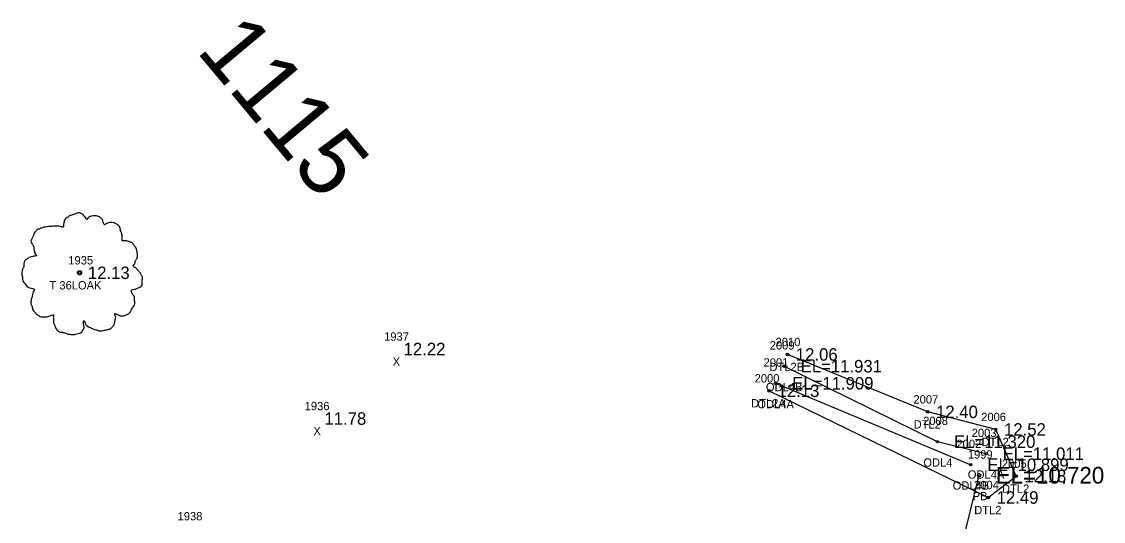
# Model space of a CAD drawing. Extents: x 2042117 to 2045853, y 303080 to 309569.
# Drawn here: x 2044100.5 to 2044230.3, y 305233.1 to 305293.1 of the extents above; entities that cross this region are included whole.
import ezdxf

# ---------------------------------------------------------------- set-up
doc = ezdxf.new("R2010")
doc.units = 0
for name, color, linetype in [('RD_EX_DR_Pipe', 7, 'Continuous'), ('RD_EX_DR_Pipe_txCode', 7, 'Continuous'), ('RD_EX_H2O', 7, 'Continuous'), ('RD_EX_H2O_txCode', 7, 'Continuous'), ('RD_EX_Misc_txCode', 7, 'Continuous'), ('RD_EX_TX_H2O_ELEV', 7, 'Continuous'), ('RD_EX_TX_Misc_ELEV', 7, 'Continuous'), ('RD_EX_TX_VEG_ELEV', 7, 'Continuous'), ('RD_EX_VEG', 7, 'Continuous'), ('RD_EX_VEG_txCode', 7, 'Continuous'), ('RD_HC_TX_Sta50', 7, 'Continuous'), ('RD_SMD_Locator', 7, 'Continuous'), ('RD_TX_Pipe_ElevEX', 7, 'Continuous')]:
    doc.layers.add(name, color=color, linetype=linetype)

msp = doc.modelspace()

# ---------------------------------------------------------------- linework, layer by layer
at = {"layer": 'RD_EX_DR_Pipe'}
msp.add_line((2044209.68, 305215.41), (2044215.36, 305238.61), dxfattribs=at)
at = {"layer": 'RD_EX_H2O'}
msp.add_line((2044190.92, 305249.65), (2044214.35, 305239.88), dxfattribs=at)
for points in [[(2044190.17, 305248.75), (2044216.46, 305235.94), (2044219.8, 305238.51), (2044217.35, 305244.11), (2044209.19, 305246.22), (2044192.36, 305253.11)], [(2044216.18, 305241.2), (2044210.35, 305242.64), (2044191.94, 305251.7)]]:
    msp.add_lwpolyline(points, dxfattribs=at)
at = {"layer": 'RD_EX_VEG'}
for centre, radius in [((2044107.4, 305262.91), 0.25), ((2044107.39, 305262.89), 0.0001)]:
    msp.add_circle(centre, radius, dxfattribs=at)
for points in [[(2044107.53, 305270.08), (2044107.23, 305270.1), (2044106.91, 305270), (2044106.66, 305269.9), (2044106.43, 305269.83), (2044106.21, 305269.73), (2044105.91, 305269.55), (2044105.68, 305269.35), (2044105.56, 305269.1), (2044105.51, 305268.88), (2044105.46, 305268.6), (2044105.46, 305268.43), (2044105.33, 305268.4), (2044105.18, 305268.43), (2044104.93, 305268.5), (2044104.68, 305268.5), (2044104.43, 305268.5), (2044104.08, 305268.48), (2044103.73, 305268.48), (2044103.46, 305268.43), (2044103.13, 305268.38), (2044102.76, 305268.25), (2044102.41, 305268.13), (2044102.11, 305267.88), (2044101.86, 305267.4), (2044101.73, 305267.05), (2044101.58, 305266.8), (2044101.73, 305266.35), (2044101.91, 305266), (2044101.93, 305265.8), (2044102.01, 305265.38), (2044102.11, 305265.16), (2044102.23, 305264.96), (2044102.16, 305264.93), (2044101.78, 305264.88), (2044101.48, 305264.78), (2044101.06, 305264.56), (2044100.83, 305264.33), (2044100.73, 305264.01), (2044100.71, 305263.66), (2044100.61, 305263.46), (2044100.53, 305263.18), (2044100.51, 305263.11), (2044100.46, 305262.78), (2044100.56, 305262.33), (2044100.58, 305261.98), (2044100.71, 305261.76), (2044100.86, 305261.58), (2044101.03, 305261.33), (2044101.43, 305261.11), (2044101.76, 305261.01), (2044101.96, 305260.98), (2044101.78, 305260.48), (2044101.73, 305260.13), (2044101.61, 305259.73), (2044101.61, 305259.66), (2044101.56, 305259.18), (2044101.71, 305258.86), (2044101.78, 305258.48), (2044101.96, 305258.26), (2044102.23, 305257.96), (2044102.56, 305257.73), (2044103.06, 305257.61), (2044103.46, 305257.63), (2044104.03, 305257.81), (2044104.28, 305257.88), (2044104.26, 305257.71), (2044104.28, 305257.33), (2044104.28, 305256.91), (2044104.43, 305256.58), (2044104.53, 305256.31), (2044104.68, 305256.06), (2044105.01, 305255.83), (2044105.41, 305255.76), (2044105.83, 305255.61), (2044106.28, 305255.53), (2044106.78, 305255.51), (2044107.38, 305255.66), (2044107.65, 305255.78), (2044107.75, 305255.96), (2044107.95, 305256.33), (2044107.9, 305256.56), (2044107.93, 305257.16), (2044108.03, 305256.98), (2044108.2, 305256.63), (2044108.7, 305256.33), (2044109.1, 305256.16), (2044109.58, 305256.01), (2044109.88, 305255.93), (2044110.35, 305256.01), (2044110.73, 305256.08), (2044111.1, 305256.21), (2044111.4, 305256.48), (2044111.58, 305256.76), (2044111.63, 305257.03), (2044111.7, 305257.41), (2044111.75, 305257.58)], [(2044111.75, 305257.58), (2044111.68, 305257.76), (2044111.63, 305258.01), (2044111.7, 305257.98), (2044111.88, 305257.93), (2044112.15, 305257.81), (2044112.38, 305257.73), (2044112.7, 305257.76), (2044112.98, 305257.86), (2044113.43, 305258.13), (2044113.7, 305258.61), (2044113.98, 305259.01), (2044114.05, 305259.33), (2044114, 305259.56), (2044113.98, 305260.06), (2044113.78, 305260.31), (2044113.73, 305260.43), (2044113.63, 305260.83), (2044113.7, 305260.88), (2044113.98, 305260.93), (2044114.35, 305261.06), (2044114.63, 305261.18), (2044114.85, 305261.36), (2044114.93, 305261.58), (2044114.9, 305261.98), (2044114.95, 305262.38), (2044114.88, 305262.53), (2044114.78, 305262.68), (2044114.7, 305262.88), (2044114.55, 305263.03), (2044114.45, 305263.18), (2044114.35, 305263.28), (2044114.23, 305263.43), (2044114.05, 305263.56), (2044113.9, 305263.61), (2044113.85, 305263.76), (2044114, 305263.96), (2044114.05, 305264.06), (2044114.08, 305264.28), (2044114.3, 305264.63), (2044114.35, 305265.03), (2044114.3, 305265.46), (2044114.25, 305265.73), (2044114.1, 305266), (2044113.9, 305266.25), (2044113.78, 305266.43), (2044113.6, 305266.55), (2044113.28, 305266.68), (2044113.03, 305266.73), (2044112.68, 305266.73), (2044112.48, 305266.78), (2044112.5, 305266.83), (2044112.5, 305266.98), (2044112.5, 305267.25), (2044112.43, 305267.7), (2044112.28, 305268.2), (2044112.28, 305268.23), (2044112.18, 305268.48), (2044111.95, 305268.68), (2044111.78, 305268.78), (2044111.58, 305268.9), (2044111.33, 305268.93), (2044111.03, 305268.93), (2044110.75, 305268.88), (2044110.55, 305268.78), (2044110.38, 305268.65), (2044110.3, 305268.8), (2044110.2, 305269.1), (2044110.15, 305269.25), (2044110, 305269.43), (2044109.78, 305269.63), (2044109.33, 305269.75), (2044108.7, 305269.68), (2044108.4, 305269.48), (2044108.25, 305269.3), (2044108.2, 305269.43), (2044108, 305269.63), (2044107.9, 305269.8), (2044107.73, 305269.93), (2044107.58, 305270.03), (2044107.48, 305270.08)]]:
    msp.add_spline(points, degree=3, dxfattribs=at)
at = {"layer": 'RD_SMD_Locator'}
for centre, radius in [((2044107.4, 305262.91), 0.15), ((2044192.36, 305253.11), 0.15), ((2044191.94, 305251.7), 0.15), ((2044190.92, 305249.65), 0.15), ((2044190.17, 305248.75), 0.15), ((2044209.19, 305246.22), 0.15), ((2044217.35, 305244.11), 0.15), ((2044210.35, 305242.64), 0.15), ((2044216.18, 305241.2), 0.15), ((2044214.35, 305239.88), 0.15), ((2044215.36, 305238.61), 0.2), ((2044219.8, 305238.51), 0.15), ((2044216.46, 305235.94), 0.15)]:
    msp.add_circle(centre, radius, dxfattribs=at)

# ---------------------------------------------------------------- texts
at = {"layer": 'RD_EX_DR_Pipe_txCode'}
for s, p in [('1999', (2044214.01, 305240.61)), ('PB', (2044214.58, 305235.61))]:
    msp.add_text(s, height=1, dxfattribs=at).set_placement(p)
at = {"layer": 'RD_EX_H2O_txCode'}
for s, p in [('2009', (2044190.23, 305253.7)), ('2010', (2044190.93, 305254.11)), ('2001', (2044189.49, 305251.65)), ('DTL2B', (2044190.19, 305251.11)), ('2000', (2044188.42, 305249.75)), ('ODL4B', (2044189.77, 305248.7)), ('2007', (2044207.48, 305247.22)), ('DTL2A', (2044187.99, 305246.75)), ('ODL4A', (2044188.74, 305246.65)), ('2008', (2044208.64, 305244.64)), ('2006', (2044215.61, 305245.11)), ('DTL2', (2044207.5, 305244.22)), ('2003', (2044214.47, 305243.2)), ('2002', (2044212.64, 305241.88)), ('DTL2', (2044215.65, 305242.11)), ('ODL4', (2044208.66, 305239.64)), ('2005', (2044218.09, 305239.51)), ('ODL4A', (2044214, 305238.2)), ('ODL4B', (2044212.18, 305236.88)), ('2004', (2044214.75, 305236.94)), ('DTL2', (2044218.1, 305236.51)), ('DTL2', (2044214.77, 305233.94))]:
    msp.add_text(s, height=1, dxfattribs=at).set_placement(p)
at = {"layer": 'RD_EX_Misc_txCode'}
for s, p in [('1937', (2044143.95, 305254.76)), ('X', (2044144.98, 305251.76)), ('1936', (2044134.42, 305246.42)), ('X', (2044135.47, 305243.42)), ('1938', (2044119.17, 305233.2))]:
    msp.add_text(s, height=1, dxfattribs=at).set_placement(p)
at = {"layer": 'RD_EX_TX_H2O_ELEV'}
for s, p in [('12.06', (2044193.36, 305252.36)), ('EL=11.931', (2044193.94, 305250.95)), ('12.13', (2044191.17, 305248)), ('EL=11.909', (2044192.92, 305248.9)), ('12.40', (2044210.19, 305245.47)), ('12.52', (2044218.35, 305243.36)), ('EL=11.320', (2044212.35, 305241.89)), ('EL=11.011', (2044218.18, 305240.45)), ('EL=10.899', (2044216.35, 305239.13)), ('12.18', (2044220.8, 305237.76)), ('12.49', (2044217.46, 305235.19))]:
    msp.add_text(s, height=1.5, dxfattribs=at).set_placement(p)
at = {"layer": 'RD_EX_TX_Misc_ELEV'}
for s, p in [('12.22', (2044146.29, 305253.01)), ('11.78', (2044136.79, 305244.67))]:
    msp.add_text(s, height=1.5, dxfattribs=at).set_placement(p)
at = {"layer": 'RD_EX_TX_VEG_ELEV'}
msp.add_text('12.13', height=1.5, dxfattribs=at).set_placement((2044108.4, 305262.16))
at = {"layer": 'RD_EX_VEG_txCode'}
for s, p in [('1935', (2044106.05, 305263.91)), ('T 36LOAK', (2044103.79, 305260.91))]:
    msp.add_text(s, height=1, dxfattribs=at).set_placement(p)
at = {"layer": 'RD_HC_TX_Sta50'}
msp.add_text('1115', height=8, rotation=309.8684, dxfattribs=at).set_placement((2044121.3, 305289.55))
at = {"layer": 'RD_TX_Pipe_ElevEX'}
msp.add_text('EL=10.720', height=2, dxfattribs=at).set_placement((2044217.36, 305237.61))

doc.saveas('drawing.dxf')
